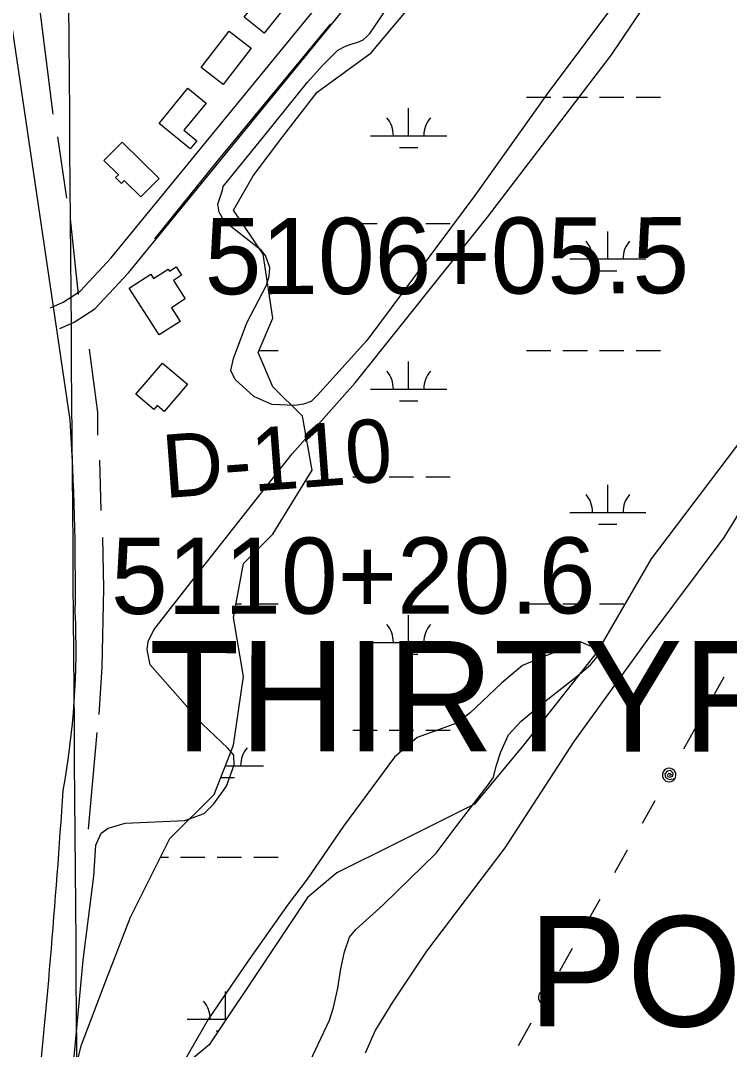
# Model space of a CAD drawing. Extents: x 3535183 to 3573198, y 534952 to 560562.
# Drawn here: x 3555062 to 3555992, y 549561 to 550912 of the extents above; entities that cross this region are included whole.
import ezdxf

# ---------------------------------------------------------------- set-up
doc = ezdxf.new("R2010")
doc.units = 0
for name, color, linetype in [('V-BLDG-OTLN', 7, 'Continuous'), ('V-GRID-MAJR', 7, 'Continuous'), ('V-RIVR-IDEN', 7, 'Continuous'), ('V-RIVR-RANG-IDEN', 7, 'Continuous'), ('V-ROAD-CNTR', 7, 'Continuous'), ('V-SITE-VEGE', 7, 'Continuous'), ('V-SURV-IDEN', 7, 'Continuous'), ('V-TOPO-SHOR', 7, 'Continuous'), ('V-UTIL-LINE', 7, 'Continuous'), ('V-WETL-SWMP', 7, 'Continuous')]:
    doc.layers.add(name, color=color, linetype=linetype)

msp = doc.modelspace()

# ---------------------------------------------------------------- linework, layer by layer
at = {"layer": 'V-BLDG-OTLN'}
for points in [[(3555423.627, 550949.18), (3555381.196, 550896.102), (3555354.978, 550917.062), (3555397.4080000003, 550970.14)], [(3555364.0670000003, 550876.196), (3555327.477, 550828.584), (3555298.676, 550850.7170000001), (3555335.268, 550898.329)], [(3555243.327, 550777.402), (3555281.088, 550823.458), (3555305.015, 550803.838), (3555275.988, 550768.436), (3555292.833, 550754.62), (3555284.102, 550743.969)], [(3555195.0100000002, 550752.777), (3555243.417, 550704.883), (3555219.631, 550680.841), (3555197.775, 550702.464), (3555193.952, 550698.5970000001), (3555186.3000000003, 550706.167), (3555190.001, 550709.908), (3555171.098, 550728.611)], [(3555243.704, 550499.665), (3555204.2430000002, 550561.224), (3555232.556, 550579.375), (3555236.267, 550573.585), (3555255.471, 550585.8960000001), (3555256.989, 550583.524), (3555265.8510000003, 550589.206), (3555273.037, 550577.993), (3555262.1380000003, 550571.007), (3555277.631, 550546.836), (3555259.682, 550535.331), (3555271.233, 550517.313)], [(3555212.973, 550421.786), (3555248.011, 550462.7660000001), (3555280.6040000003, 550434.901), (3555250.018, 550399.127), (3555240.89, 550406.929), (3555236.437, 550401.723)]]:
    msp.add_lwpolyline(points, close=True, dxfattribs=at)
at = {"layer": 'V-GRID-MAJR'}
msp.add_spline([(3555204.1780000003, 540472.404), (3555158.363, 546529.794), (3555112.522, 552590.651), (3555066.681, 558651.524), (3555066.6550000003, 558654.975)], degree=3, dxfattribs=at)
at = {"layer": 'V-ROAD-CNTR'}
for points in [[(3555126.839707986, 550388.145197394), (3555043.144875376, 550955.24606319)], [(3555100.963759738, 550535.2899031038), (3555117.423726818, 550542.7278882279), (3555139.78768209, 550557.1168594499), (3555180.4496007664, 550601.0037716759), (3555469.528022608, 550954.6240644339)], [(3555113.3177350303, 550507.9519577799), (3555131.793698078, 550516.3019410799), (3555159.213643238, 550533.9409058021), (3555203.08755549, 550581.2958110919), (3555492.7539761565, 550935.6361024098)]]:
    msp.add_lwpolyline(points, dxfattribs=at)
for centre, radius, start, end in [((3551571.7122987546, 550168.4804453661), 3561.9072838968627, 359.47085578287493, 3.535689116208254), ((3554085.189584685, 550089.196905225), 1049.3040594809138, 349.69592270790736, 2.5338977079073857), ((3543050.1643414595, 550698.9540709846), 12093.726539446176, 354.1145628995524, 356.21922401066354)]:
    msp.add_arc(centre, radius, start, end, dxfattribs=at)
at = {"layer": 'V-SITE-VEGE'}
for points in [[(3555130.543, 549537.865), (3555143.679, 549678.683), (3555157.622, 549789.076), (3555160.3170000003, 549829.643), (3555167.325, 549845.251), (3555176.681, 549851.8910000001), (3555198.906, 549858.5430000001), (3555277.301, 549862.122), (3555302.647, 549871.115), (3555315.117, 549883.997), (3555331.8680000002, 549907.025), (3555341.983, 549935.117), (3555341.5840000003, 549947.9890000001), (3555333.775, 549956.951), (3555300.593, 549988.517), (3555231.876, 550066.464), (3555227.957, 550086.354), (3555229.1180000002, 550096.885), (3555236.515, 550112.493), (3555294.179, 550186.264), (3555418.0700000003, 550343.56), (3555500.676, 550436.855), (3555674.443, 550654.262), (3555837.294, 550867.371), (3555982.196, 551082.804)], [(3555852.965, 550950.598), (3555754.0300000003, 550817.814), (3555657.83, 550682.6950000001), (3555516.049, 550492.112), (3555450.98, 550420.2390000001), (3555443.187, 550412.426), (3555433.0470000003, 550408.51), (3555421.734, 550406.936), (3555391.299, 550408.459), (3555367.876, 550418.574), (3555343.267, 550441.172), (3555337.791, 550452.87), (3555340.8910000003, 550468.871), (3555358.781, 550515.324), (3555384.469, 550564.91), (3555387.965, 550576.618), (3555388.731, 550588.325), (3555383.248, 550603.924), (3555377.778, 550610.55), (3555337.551, 550642.101), (3555328.1750000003, 550650.674), (3555322.312, 550660.814), (3555320.737, 550671.345), (3555326.566, 550689.689), (3555327.342, 550694.372), (3555382.269, 550761.942), (3555438.366, 550831.461), (3555458.236, 550853.727), (3555478.112, 550873.65), (3555488.247, 550878.735), (3555496.828, 550881.8690000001), (3555504.238, 550884.218), (3555511.256, 550887.3470000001), (3555515.545, 550890.866), (3555520.22, 550895.554), (3555582.142, 550987.3200000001)], [(3556496.217, 550920.154), (3556450.823, 550875.325), (3556366.268, 550781.64), (3556268.4760000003, 550660.2490000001), (3556194.058, 550567.74), (3556088.893, 550402.661), (3555984.5100000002, 550233.681), (3555884.779, 550100.196), (3555787.775, 549965.936), (3555697.02, 549826.219), (3555594.561, 549690.394), (3555549.765, 549623.657), (3555527.565, 549586.9720000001), (3555513.9390000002, 549556.5380000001)], [(3555437.727, 549537.734), (3555466.946, 549599.823), (3555472.396, 549616.61), (3555477.8370000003, 549641.987), (3555482.109, 549667.362), (3555486.773, 549689.617), (3555493.392, 549708.748), (3555501.578, 549718.904), (3555537.463, 549751.334), (3555606.882, 549818.922), (3555633.393, 549854.078), (3555676.669, 549910.711), (3555682.5160000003, 549918.914), (3555686.0160000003, 549933.358), (3555691.855, 549952.099), (3555701.985, 549974.357), (3555718.752, 549992.328), (3555745.275, 550014.602), (3555768.289, 550032.578), (3555792.082, 550051.333), (3555809.634, 550066.572), (3555818.213, 550076.728), (3555818.991, 550082.194), (3555814.299, 550088.826), (3555797.411, 550096.2170000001), (3555748.671, 550077.453), (3555720.6010000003, 550065.726), (3555693.3170000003, 550042.693), (3555667.597, 550018.485), (3555651.6180000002, 550003.258), (3555633.688, 549989.981), (3555610.294, 549980.99)], [(3555610.294, 549980.99), (3555582.22, 549970.822), (3555552.208, 549945.054), (3555485.593, 549854.506), (3555437.6780000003, 549785.036), (3555412.7460000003, 549752.2490000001), (3555360.1550000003, 549677.704), (3555308.347, 549601.601), (3555258.498, 549514.966)]]:
    msp.add_lwpolyline(points, dxfattribs=at)
at = {"layer": 'V-TOPO-SHOR'}
for p, q in [((3555104.392, 550789.527), (3555083.8140000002, 550953.952)), ((3555122.47, 550679.191), (3555110.67, 550759.8960000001)), ((3555137.838, 550552.8640000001), (3555127.185, 550651.899)), ((3555167.35, 550269.287), (3555165.708, 550335.1900000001)), ((3555150.72, 549850.451), (3555162.259, 549977.593))]:
    msp.add_line(p, q, dxfattribs=at)
for points in [[(3555237.627, 550625.605), (3555319.789, 550727.4990000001), (3555468.93, 550908.253)], [(3555162.937, 550367.944), (3555162.9, 550397.58), (3555151.875, 550481.018)], [(3555164.569, 550000.991), (3555168.7800000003, 550063.392), (3555170.989, 550166.734), (3555169.736, 550233.806)]]:
    msp.add_lwpolyline(points, dxfattribs=at)
at = {"layer": 'V-UTIL-LINE'}
for points in [[(3555984.561992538, 550050.0988734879), (3555967.995025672, 550020.40793287)], [(3555948.5040646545, 549985.47800273), (3555931.937097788, 549955.7870621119)], [(3555912.935135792, 549921.7301302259), (3555915.799130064, 549922.0071296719), (3555914.2871330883, 549923.7751261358), (3555911.5621385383, 549923.4421268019), (3555910.427140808, 549920.7431322), (3555913.3121350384, 549918.949135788), (3555917.852125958, 549920.11813345), (3555918.1901252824, 549924.3721249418), (3555914.72613221, 549927.786118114), (3555910.2651411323, 549926.757120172), (3555907.2911470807, 549923.419126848), (3555908.162145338, 549918.6751363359), (3555912.804136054, 549915.715142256), (3555920.7951200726, 549917.3451389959), (3555921.8751179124, 549920.686132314), (3555921.594118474, 549924.186125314), (3555919.994121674, 549927.3131190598), (3555917.32112702, 549929.5891145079), (3555913.979133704, 549930.6691123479), (3555910.479140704, 549930.3881129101), (3555907.3521469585, 549928.789116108), (3555905.0761515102, 549926.1151214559), (3555903.9961536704, 549922.7741281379), (3555904.2771531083, 549919.27313514), (3555905.87614991, 549916.147141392), (3555908.550144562, 549913.8711459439), (3555911.8911378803, 549912.791148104), (3555915.392130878, 549913.072147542), (3555918.518124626, 549914.6711443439), (3555920.7951200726, 549917.3451389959)], [(3555893.9301738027, 549887.67319834), (3555877.363206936, 549857.982257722)], [(3555857.8722459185, 549823.0523275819), (3555841.305279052, 549793.3613869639)], [(3555821.815318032, 549758.4324568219), (3555805.248351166, 549728.7415162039)], [(3555785.7583901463, 549693.8115860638), (3555769.1914232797, 549664.1206454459)], [(3555750.1904612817, 549630.064713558), (3555753.054455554, 549630.340713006), (3555751.542458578, 549632.1097094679), (3555748.81646403, 549631.776710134), (3555747.6814663, 549629.0777155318), (3555750.5664605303, 549627.2837191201), (3555755.1064514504, 549628.4527167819), (3555755.444450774, 549632.705708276), (3555751.9814577, 549636.1207014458), (3555747.519466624, 549635.0917035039), (3555744.5464725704, 549631.7537101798), (3555745.41647083, 549627.0087196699), (3555750.058461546, 549624.04872559), (3555758.0494455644, 549625.6787223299), (3555759.1294434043, 549629.0207156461), (3555758.848443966, 549632.5207086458), (3555757.249447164, 549635.6477023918), (3555754.5754525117, 549637.92369784), (3555751.2344591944, 549639.00369568), (3555747.7334661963, 549638.7226962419), (3555744.6074724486, 549637.12369944), (3555742.330477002, 549634.4497047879), (3555741.2514791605, 549631.1087114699), (3555741.5314786, 549627.607718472), (3555743.1314754, 549624.4817247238), (3555745.8044700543, 549622.2047292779), (3555749.1464633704, 549621.1247314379), (3555752.6464563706, 549621.405730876), (3555755.773450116, 549623.005727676), (3555758.0494455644, 549625.6787223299)], [(3555731.1854992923, 549596.0067816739), (3555714.6185324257, 549566.3158410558)]]:
    msp.add_lwpolyline(points, dxfattribs=at)
at = {"layer": 'V-WETL-SWMP'}
for p, q in [((3555725.506674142, 550811.9453181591), (3555757.506674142, 550811.9453181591)), ((3555773.506674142, 550811.9453181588), (3555805.506674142, 550811.9453181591)), ((3555821.506674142, 550811.9453181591), (3555853.506674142, 550811.9453181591)), ((3555869.506674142, 550811.9453181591), (3555901.506674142, 550811.9453181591)), ((3555570.914674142, 550761.2033181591), (3555570.914674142, 550797.2033181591)), ((3555520.914674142, 550761.2033181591), (3555620.9146741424, 550761.2033181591)), ((3555558.914674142, 550745.7723181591), (3555582.914674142, 550745.7723181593)), ((3555497.506674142, 550645.7713181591), (3555529.5066741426, 550645.7713181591)), ((3555545.506674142, 550645.7713181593), (3555577.506674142, 550645.7713181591)), ((3555593.506674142, 550645.7713181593), (3555625.506674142, 550645.7713181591)), ((3555832.350674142, 550599.3413181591), (3555832.350674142, 550635.3413181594)), ((3555782.3506741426, 550599.3413181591), (3555882.350674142, 550599.3413181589)), ((3555820.350674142, 550583.9103181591), (3555844.350674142, 550583.9103181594)), ((3555374.6740102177, 550479.2703181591), (3555399.598674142, 550479.2703181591)), ((3555725.506674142, 550479.2703181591), (3555757.506674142, 550479.2703181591)), ((3555773.506674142, 550479.2703181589), (3555805.506674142, 550479.2703181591)), ((3555821.506674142, 550479.2703181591), (3555853.506674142, 550479.2703181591)), ((3555869.506674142, 550479.2703181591), (3555901.506674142, 550479.2703181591)), ((3555570.914674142, 550428.5283181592), (3555570.914674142, 550464.5283181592)), ((3555520.914674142, 550428.5283181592), (3555620.9146741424, 550428.5283181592)), ((3555558.914674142, 550413.0973181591), (3555582.914674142, 550413.0973181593)), ((3555497.506674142, 550313.0963181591), (3555529.5066741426, 550313.0963181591)), ((3555545.506674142, 550313.0963181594), (3555577.506674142, 550313.0963181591)), ((3555593.506674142, 550313.0963181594), (3555625.506674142, 550313.0963181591)), ((3555832.350674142, 550266.6663181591), (3555832.350674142, 550302.6663181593)), ((3555782.3506741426, 550266.6663181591), (3555882.350674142, 550266.6663181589)), ((3555820.350674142, 550251.2353181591), (3555844.350674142, 550251.2353181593)), ((3555344.6021255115, 550146.5953181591), (3555351.598674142, 550146.5953181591)), ((3555367.598674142, 550146.5953181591), (3555399.598674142, 550146.5953181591)), ((3555725.506674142, 550146.5953181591), (3555757.506674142, 550146.5953181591)), ((3555773.506674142, 550146.5953181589), (3555805.506674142, 550146.5953181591)), ((3555821.506674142, 550146.5953181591), (3555853.506674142, 550146.5953181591)), ((3555570.914674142, 550095.8533181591), (3555570.914674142, 550131.8533181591)), ((3555520.914674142, 550095.8533181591), (3555620.9146741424, 550095.8533181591)), ((3555558.914674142, 550080.4223181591), (3555582.914674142, 550080.4223181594)), ((3555497.506674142, 549980.4213181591), (3555529.5066741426, 549980.4213181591)), ((3555545.506674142, 549980.4213181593), (3555577.506674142, 549980.4213181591)), ((3555593.506674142, 549980.4213181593), (3555625.506674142, 549980.4213181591)), ((3555330.571277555, 549933.9913181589), (3555380.442674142, 549933.9913181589)), ((3555324.398733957, 549918.5603181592), (3555342.442674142, 549918.5603181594)), ((3555245.285777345, 549813.9203181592), (3555255.598674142, 549813.9203181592)), ((3555271.598674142, 549813.9203181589), (3555303.598674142, 549813.9203181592)), ((3555319.598674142, 549813.9203181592), (3555351.598674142, 549813.9203181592)), ((3555367.598674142, 549813.9203181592), (3555399.598674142, 549813.9203181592)), ((3555330.442674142, 549601.3163181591), (3555330.442674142, 549637.3163181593)), ((3555280.4426741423, 549601.3163181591), (3555331.595017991, 549601.3163181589)), ((3555318.442674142, 549585.8853181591), (3555321.3077732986, 549585.8853181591))]:
    msp.add_line(p, q, dxfattribs=at)
for points in [[(3556572.788, 551082.7), (3556211.725, 550631.371), (3555889.347, 550205.832), (3555818.424, 550083.328), (3555721.711, 549960.825), (3555657.235, 549883.454), (3555554.074, 549831.8740000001), (3555476.703, 549793.188), (3555438.018, 549760.95), (3555386.437, 549683.58), (3555309.0670000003, 549567.524), (3555231.696, 549503.0480000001)], [(3555128.535, 549515.943), (3555141.43, 549567.524), (3555173.668, 549651.3420000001), (3555205.906, 549735.16), (3555257.486, 549838.321), (3555315.514, 549896.349), (3555341.305, 549960.825), (3555354.2, 550051.091), (3555341.305, 550128.461), (3555354.2, 550199.384), (3555392.8850000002, 550238.0700000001), (3555444.465, 550321.888), (3555431.5700000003, 550392.811), (3555392.8850000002, 550431.497), (3555373.542, 550476.629), (3555392.8850000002, 550521.762), (3555379.99, 550605.581), (3555341.305, 550663.609), (3555367.095, 550708.742), (3555405.7800000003, 550760.322), (3555450.913, 550818.35), (3555521.836, 550869.931), (3555586.312, 550947.301)]]:
    msp.add_lwpolyline(points, dxfattribs=at)
for centre, radius, start, end in [((3555515.67173804, 550761.6781213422), 35.24628790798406, 359.2281799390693, 40.771838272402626), ((3555626.157610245, 550761.6781213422), 35.24628790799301, 139.2281769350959, 180.77183526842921), ((3555777.107738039, 550599.8161213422), 35.24628790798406, 359.2281799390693, 40.771838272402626), ((3555887.5936102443, 550599.8161213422), 35.24628790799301, 139.2281769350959, 180.77183526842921), ((3555515.67173804, 550429.0031213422), 35.24628790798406, 359.2281799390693, 40.771838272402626), ((3555626.157610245, 550429.0031213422), 35.24628790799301, 139.2281769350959, 180.77183526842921), ((3555777.107738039, 550267.1411213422), 35.24628790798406, 359.2281799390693, 40.771838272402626), ((3555887.5936102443, 550267.1411213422), 35.24628790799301, 139.2281769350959, 180.77183526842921), ((3555515.67173804, 550096.3281213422), 35.24628790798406, 359.2281799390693, 40.771838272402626), ((3555626.157610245, 550096.3281213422), 35.24628790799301, 139.2281769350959, 180.77183526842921), ((3555385.6856102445, 549934.4661213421), 35.24628790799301, 139.2281769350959, 180.77183526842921), ((3555275.199738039, 549601.7911213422), 35.24628790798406, 359.2281799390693, 40.771838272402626)]:
    msp.add_arc(centre, radius, start, end, dxfattribs=at)

# ---------------------------------------------------------------- texts
at = {"layer": 'V-RIVR-IDEN'}
msp.add_text('THIRTYFIVE MILE', height=144.99971199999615, rotation=359.97625735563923, dxfattribs=at).set_placement((3555230.3205010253, 549952.8380680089))
msp.add_text('POINT', height=144.9997119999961, dxfattribs=at).set_placement((3555728.016505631, 549591.5197906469))
at = {"layer": 'V-RIVR-RANG-IDEN'}
msp.add_text('D-110', height=82.99999999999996, rotation=4.291325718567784, dxfattribs=at).set_placement((3555250.6123708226, 550285.2940822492))
at = {"layer": 'V-SURV-IDEN'}
for s, height, rotation, p in [('5106+05.5', 100.00000000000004, 0.1276576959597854, (3555303.338299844, 550552.9615404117)), ('5110+20.6', 100.00000000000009, 0.06210677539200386, (3555180.3081294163, 550133.2144641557))]:
    msp.add_text(s, height=height, rotation=rotation, dxfattribs=at).set_placement(p)

doc.saveas('drawing.dxf')
